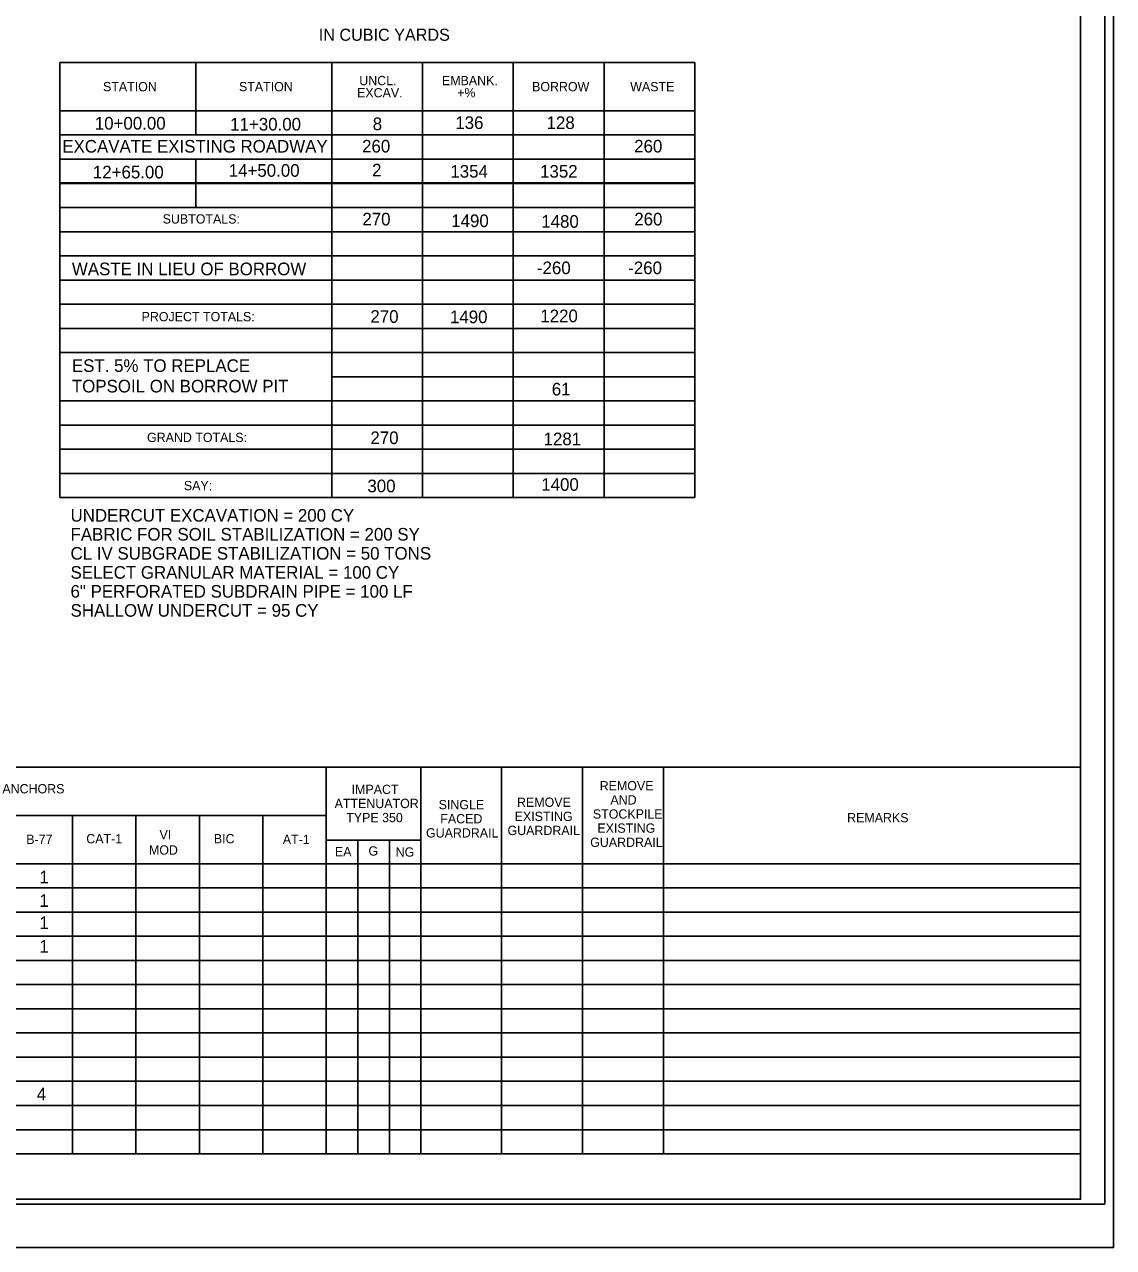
# Model space of a CAD drawing. Extents: x 573885.1 to 573944.9, y -53259.7 to -53181.6.
# Drawn here: x 573925.66 to 573936.92, y -53259.73 to -53247.09 of the extents above; entities that cross this region are included whole.
import ezdxf

# ---------------------------------------------------------------- set-up
doc = ezdxf.new("R2010")
doc.units = 0
for name, color, linetype in [('Prop DSN Text', 7, 'Continuous'), ('Sheet Cutting Line CELL', 7, 'Continuous'), ('Sheet Plot Border Inside CELL', 7, 'Continuous'), ('Sheet Plot Border Outside CELL', 7, 'Continuous'), ('Sheet Summary Combination CELL', 7, 'Continuous'), ('Sheet Summary Combination Grid CELL', 7, 'Continuous')]:
    doc.layers.add(name, color=color, linetype=linetype)

msp = doc.modelspace()

# ---------------------------------------------------------------- linework, layer by layer
at = {"layer": 'Sheet Cutting Line CELL'}
msp.add_line((573903.239, -53259.733), (573936.919, -53259.733), dxfattribs=at)
at = {"layer": 'Sheet Plot Border Inside CELL'}
msp.add_lwpolyline([(573936.829, -53238.182), (573903.499, -53238.182), (573903.499, -53259.284), (573936.829, -53259.284)], close=True, dxfattribs=at)
at = {"layer": 'Sheet Plot Border Outside CELL'}
msp.add_lwpolyline([(573936.919, -53237.733), (573903.239, -53237.733), (573903.239, -53259.733), (573936.919, -53259.733)], close=True, dxfattribs=at)
at = {"layer": 'Sheet Summary Combination CELL'}
for p, q in [((573927.91, -53247.48), (573927.91, -53247.48)), ((573928.035, -53247.482), (573928.035, -53247.482)), ((573928.216, -53247.478), (573928.216, -53247.478)), ((573928.328, -53247.48), (573928.328, -53247.48))]:
    msp.add_line(p, q, dxfattribs=at)
msp.add_lwpolyline([(573936.579, -53238.233), (573906.579, -53238.233), (573906.579, -53259.233), (573936.579, -53259.233)], close=True, dxfattribs=at)
at = {"layer": 'Sheet Summary Combination Grid CELL'}
for p, q in [((573926.023, -53247.479), (573932.588, -53247.479)), ((573926.023, -53247.479), (573926.023, -53251.979)), ((573927.43, -53247.479), (573927.43, -53248.229)), ((573928.836, -53247.479), (573928.836, -53251.979)), ((573929.774, -53247.479), (573929.774, -53251.979)), ((573930.712, -53247.479), (573930.712, -53251.979)), ((573931.65, -53247.479), (573931.65, -53251.979)), ((573932.588, -53247.479), (573932.588, -53251.979)), ((573926.023, -53247.979), (573932.588, -53247.979)), ((573926.023, -53248.229), (573932.588, -53248.229)), ((573926.023, -53248.479), (573932.588, -53248.479)), ((573927.43, -53248.479), (573927.43, -53248.979)), ((573926.023, -53248.722), (573932.588, -53248.722)), ((573926.023, -53248.729), (573932.588, -53248.729)), ((573926.023, -53248.979), (573932.588, -53248.979)), ((573926.023, -53248.979), (573932.588, -53248.979)), ((573926.023, -53248.979), (573932.588, -53248.979)), ((573926.023, -53249.229), (573932.588, -53249.229)), ((573926.023, -53249.229), (573932.588, -53249.229)), ((573926.023, -53249.479), (573932.588, -53249.479)), ((573926.023, -53249.729), (573932.588, -53249.729)), ((573926.023, -53249.979), (573932.588, -53249.979)), ((573926.023, -53249.979), (573932.588, -53249.979)), ((573926.023, -53249.979), (573932.588, -53249.979)), ((573926.023, -53249.979), (573932.588, -53249.979)), ((573926.023, -53250.229), (573932.588, -53250.229)), ((573926.023, -53250.479), (573932.588, -53250.479)), ((573928.836, -53250.729), (573932.588, -53250.729)), ((573926.023, -53250.979), (573932.588, -53250.979)), ((573926.023, -53251.229), (573932.588, -53251.229)), ((573926.023, -53251.479), (573932.588, -53251.479)), ((573926.023, -53251.729), (573932.588, -53251.729)), ((573926.023, -53251.979), (573932.588, -53251.979)), ((573906.579, -53254.764), (573936.579, -53254.764)), ((573928.778, -53254.764), (573928.778, -53258.764)), ((573929.755, -53254.764), (573929.755, -53258.764)), ((573930.591, -53254.764), (573930.591, -53258.764)), ((573931.427, -53254.764), (573931.427, -53258.764)), ((573932.264, -53254.764), (573932.264, -53258.764)), ((573928.778, -53255.264), (573919.235, -53255.264)), ((573926.153, -53255.264), (573926.153, -53258.764)), ((573926.809, -53255.264), (573926.809, -53258.764)), ((573927.466, -53255.264), (573927.466, -53258.764)), ((573928.122, -53255.264), (573928.122, -53258.764)), ((573928.778, -53255.519), (573929.75, -53255.519)), ((573929.103, -53255.519), (573929.105, -53258.764)), ((573929.43, -53255.519), (573929.432, -53258.764)), ((573906.579, -53255.764), (573936.579, -53255.764)), ((573906.579, -53256.014), (573936.579, -53256.014)), ((573906.579, -53256.264), (573936.579, -53256.264)), ((573906.579, -53256.514), (573936.579, -53256.514)), ((573906.579, -53256.764), (573936.579, -53256.764)), ((573906.579, -53257.014), (573936.579, -53257.014)), ((573906.579, -53257.264), (573936.579, -53257.264)), ((573908.923, -53257.514), (573936.579, -53257.514)), ((573906.579, -53257.764), (573936.579, -53257.764)), ((573906.579, -53258.014), (573936.579, -53258.014)), ((573906.579, -53258.264), (573936.579, -53258.264)), ((573906.579, -53258.514), (573936.579, -53258.514)), ((573906.579, -53258.764), (573936.579, -53258.764))]:
    msp.add_line(p, q, dxfattribs=at)

# ---------------------------------------------------------------- texts
at = {"layer": 'Prop DSN Text'}
for s, height, p in [('10+00.00', 0.1305, (573926.384, -53248.173)), ('11+30.00', 0.1305, (573927.784, -53248.183)), ('8', 0.131, (573929.258, -53248.179)), ('136', 0.1305, (573930.112, -53248.167)), ('128', 0.1305, (573931.056, -53248.167)), ('EXCAVATE EXISTING ROADWAY', 0.1305, (573926.048, -53248.411)), ('260', 0.1305, (573929.148, -53248.41)), ('260', 0.1305, (573931.962, -53248.41)), ('2', 0.131, (573929.251, -53248.658)), ('12+65.00', 0.1305, (573926.364, -53248.678)), ('14+50.00', 0.1305, (573927.769, -53248.661)), ('1354', 0.1305, (573930.061, -53248.67)), ('1352', 0.1305, (573930.989, -53248.67)), ('270', 0.1305, (573929.151, -53249.164)), ('260', 0.1305, (573931.963, -53249.164)), ('1490', 0.1305, (573930.07, -53249.181)), ('1480', 0.1305, (573931.001, -53249.188)), ('-260', 0.1305, (573930.956, -53249.668)), ('-260', 0.1305, (573931.9, -53249.668)), ('WASTE IN LIEU OF BORROW', 0.1305, (573926.147, -53249.679)), ('270', 0.1305, (573929.234, -53250.171)), ('1490', 0.1305, (573930.057, -53250.175)), ('1220', 0.1305, (573930.991, -53250.165)), ('EST. 5% TO REPLACE ', 0.1305, (573926.147, -53250.679)), ('TOPSOIL ON BORROW PIT', 0.1305, (573926.147, -53250.891)), ('61', 0.1305, (573931.11, -53250.922)), ('270', 0.1305, (573929.234, -53251.425)), ('1281', 0.1305, (573931.025, -53251.437)), ('300', 0.1305, (573929.203, -53251.923)), ('1400', 0.1305, (573931.001, -53251.908)), ('UNDERCUT EXCAVATION = 200 CY', 0.1305, (573926.133, -53252.227)), ('FABRIC FOR SOIL STABILIZATION = 200 SY', 0.1305, (573926.133, -53252.423)), ('CL IV SUBGRADE STABILIZATION = 50 TONS', 0.1305, (573926.133, -53252.62)), ('SELECT GRANULAR MATERIAL = 100 CY', 0.1305, (573926.133, -53252.817)), ('6" PERFORATED SUBDRAIN PIPE = 100 LF', 0.1305, (573926.133, -53253.013)), ('SHALLOW UNDERCUT = 95 CY', 0.1305, (573926.133, -53253.21)), ('1', 0.131, (573925.811, -53255.968)), ('1', 0.131, (573925.811, -53256.21)), ('1', 0.131, (573925.811, -53256.44)), ('1', 0.131, (573925.811, -53256.683)), ('4', 0.131, (573925.784, -53258.211))]:
    msp.add_text(s, height=height, dxfattribs=at).set_placement(p)
at = {"layer": 'Sheet Summary Combination CELL'}
for s, height, p in [('IN CUBIC YARDS', 0.125, (573928.7, -53247.255)), ('UNCL.', 0.096, (573929.119, -53247.714)), ('EMBANK.', 0.096, (573929.974, -53247.714)), ('STATION', 0.096, (573926.469, -53247.777)), ('STATION', 0.096, (573927.875, -53247.777)), ('EXCAV.', 0.096, (573929.096, -53247.84)), ('+%', 0.096, (573930.132, -53247.84)), ('BORROW', 0.096, (573930.906, -53247.777)), ('WASTE', 0.096, (573931.921, -53247.777)), ('SUBTOTALS:', 0.096, (573927.086, -53249.145)), ('PROJECT TOTALS:', 0.096, (573926.868, -53250.155)), ('GRAND TOTALS:', 0.096, (573926.924, -53251.404)), ('SAY:', 0.096, (573927.305, -53251.902)), ('ANCHORS', 0.096, (573925.428, -53255.037)), ('IMPACT', 0.096, (573929.04, -53255.043)), ('REMOVE', 0.096, (573931.605, -53255.006)), ('ATTENUATOR', 0.096, (573928.864, -53255.189)), ('SINGLE', 0.096, (573929.94, -53255.201)), ('REMOVE', 0.096, (573930.75, -53255.176)), ('AND', 0.096, (573931.716, -53255.152)), ('EXISTING', 0.096, (573930.726, -53255.322)), ('STOCKPILE', 0.096, (573931.535, -53255.298)), ('TYPE 350', 0.096, (573928.984, -53255.335)), ('FACED', 0.096, (573929.957, -53255.347)), ('EXISTING', 0.096, (573931.581, -53255.444)), ('REMARKS', 0.096, (573934.164, -53255.336)), ('B-77', 0.096, (573925.675, -53255.56)), ('CAT-1', 0.096, (573926.296, -53255.553)), ('VI', 0.096, (573927.053, -53255.512)), ('BIC', 0.096, (573927.615, -53255.553)), ('AT-1', 0.096, (573928.328, -53255.561)), ('GUARDRAIL', 0.096, (573929.809, -53255.493)), ('GUARDRAIL', 0.096, (573930.652, -53255.468)), ('MOD', 0.096, (573926.944, -53255.67)), ('EA', 0.096, (573928.867, -53255.687)), ('G', 0.096, (573929.214, -53255.68)), ('NG', 0.096, (573929.495, -53255.691)), ('GUARDRAIL', 0.096, (573931.507, -53255.59))]:
    msp.add_text(s, height=height, dxfattribs=at).set_placement(p)

doc.saveas('drawing.dxf')
